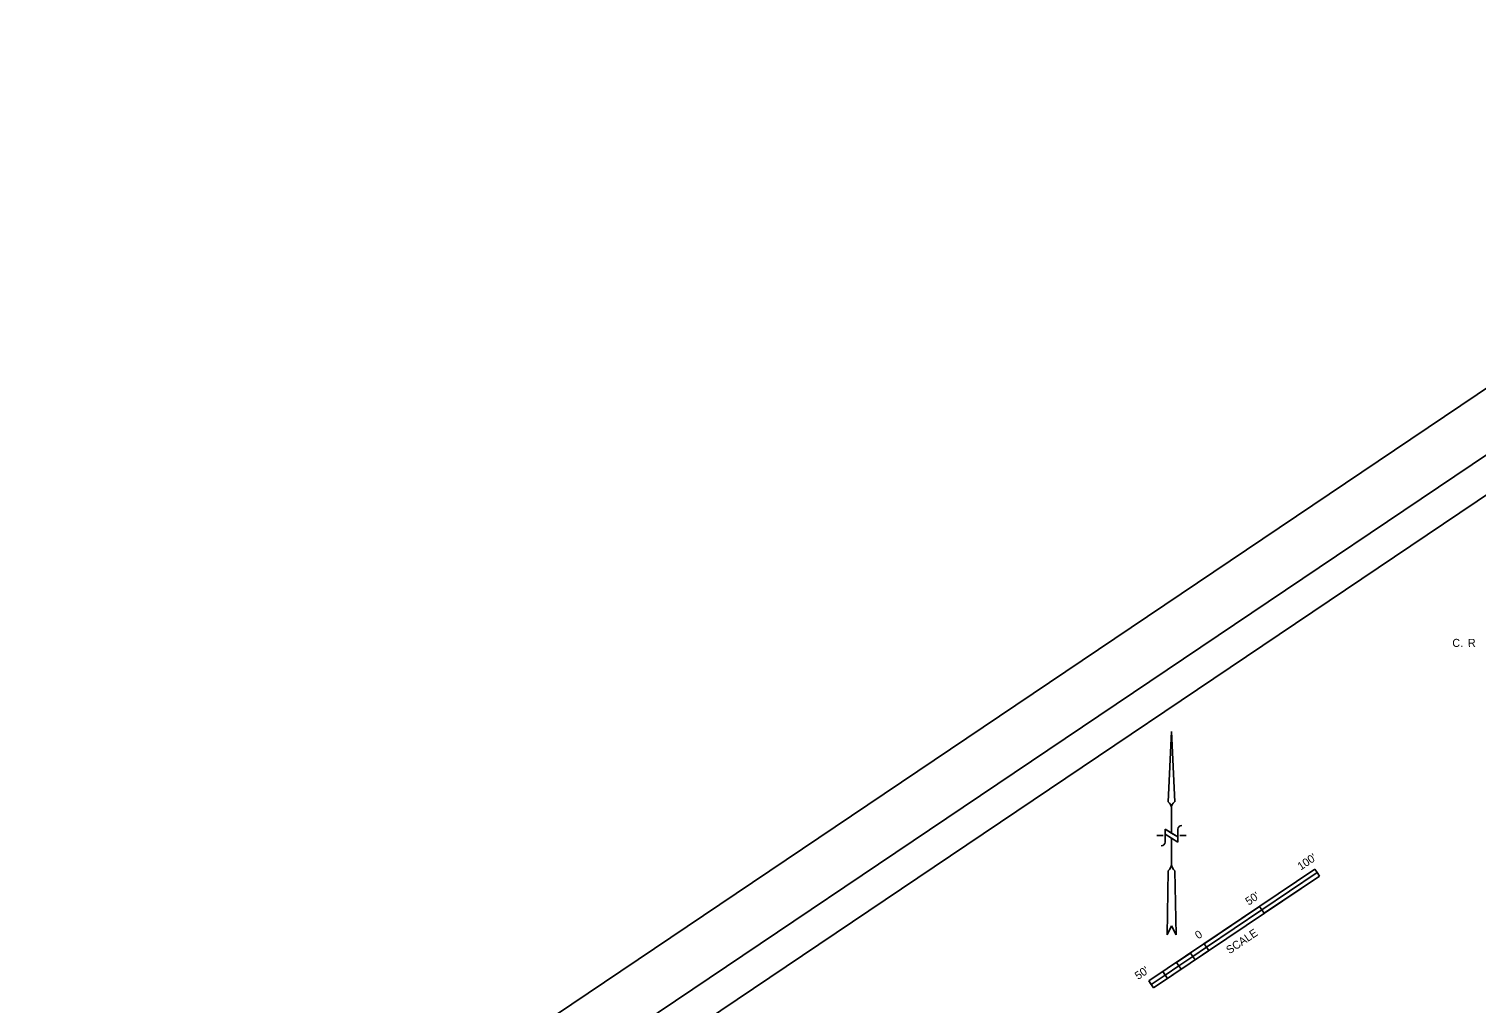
# Model space of a CAD drawing. Extents: x 2150215 to 2152378, y 141356 to 143523.
# Drawn here: x 2150215 to 2151300, y 142627 to 143357 of the extents above; entities that cross this region are included whole.
import ezdxf

# ---------------------------------------------------------------- set-up
doc = ezdxf.new("R2010")
doc.units = 0
for name, color, linetype in [('PR_Align_2_Label', 7, 'Continuous'), ('SHT_North_Arrow', 7, 'Continuous'), ('SHT_Plot_Shape_Full', 7, 'Continuous'), ('SHT_Plot_Shape_Half', 7, 'Continuous'), ('SHT_Scale', 7, 'Continuous'), ('SHT_Sheet_Border', 7, 'Continuous')]:
    doc.layers.add(name, color=color, linetype=linetype)

msp = doc.modelspace()

# ---------------------------------------------------------------- linework, layer by layer
at = {"layer": 'SHT_North_Arrow'}
for p, q in [((2151069.2, 142777.7), (2151071.6, 142830.6)), ((2151071.6, 142830.6), (2151069.2, 142777.7)), ((2151071.6, 142830.6), (2151074, 142777.7)), ((2151074, 142777.7), (2151071.6, 142830.6)), ((2151071.6, 142754.3), (2151071.6, 142773.1)), ((2151065.4, 142752.4), (2151060.6, 142752.4)), ((2151076.4, 142751.5), (2151066.8, 142757.2)), ((2151066.8, 142757.2), (2151076.4, 142751.5)), ((2151066.8, 142757.2), (2151066.8, 142747.6)), ((2151071.6, 142754.3), (2151066.8, 142757.2)), ((2151066.8, 142757.2), (2151066.8, 142753.4)), ((2151076.4, 142747.6), (2151066.8, 142753.4)), ((2151076.4, 142751.5), (2151071.6, 142754.3)), ((2151076.4, 142757.2), (2151076.4, 142747.6)), ((2151082.6, 142752.4), (2151077.8, 142752.4)), ((2151071.6, 142730.8), (2151071.6, 142750.5)), ((2151076.4, 142747.6), (2151076.4, 142751.5)), ((2151068.3, 142678.1), (2151069.2, 142726)), ((2151069.2, 142726), (2151068.3, 142678.1)), ((2151075, 142678.1), (2151074, 142726)), ((2151075, 142678.1), (2151074, 142726)), ((2151068.3, 142678.1), (2151071.6, 142684.8)), ((2151068.3, 142678.1), (2151071.6, 142684.8)), ((2151071.6, 142684.8), (2151075, 142678.1)), ((2151071.6, 142684.8), (2151075, 142678.1))]:
    msp.add_line(p, q, dxfattribs=at)
for points in [[(2151066.8, 142753.4), (2151071.6, 142750.5), (2151076.4, 142747.6)], [(2151071.6, 142730.8), (2151071.6, 142730.8), (2151071.6, 142730.8)]]:
    msp.add_lwpolyline(points, dxfattribs=at)
for centre, radius, start, end in [((2151065.8, 142773.1), 5.76, 0.0232, 54.4034), ((2151065.8, 142773.1), 5.76, 0.0232, 54.4034), ((2151077.3, 142773.1), 5.76, 125.6431, 180.0232), ((2151077.3, 142773.1), 5.76, 125.6431, 180.0232), ((2151079.3, 142757.2), 2.88, 90.0232, 180.0232), ((2151063.9, 142747.6), 2.88, 270.0232, 0.0232), ((2151063.2, 142732), 8.43, 314.9799, 352.4421), ((2151063.2, 142732), 8.43, 314.9799, 352.0822), ((2151080, 142732), 8.43, 187.6043, 225.0665), ((2151080, 142732), 8.43, 187.9642, 225.0665)]:
    msp.add_arc(centre, radius, start, end, dxfattribs=at)
at = {"layer": 'SHT_Plot_Shape_Full'}
msp.add_lwpolyline([(2150214.9, 142351.9), (2151708, 143357.2), (2152378.2, 142361.7), (2150885.1, 141356.5)], close=True, dxfattribs=at)
at = {"layer": 'SHT_Plot_Shape_Half'}
msp.add_lwpolyline([(2150305.9, 142363.4), (2151716.1, 143312.8), (2152330.4, 142400.3), (2150920.2, 141451)], close=True, dxfattribs=at)
at = {"layer": 'SHT_Scale'}
for p, q in [((2151054.7, 142643.5), (2151179.1, 142727.3)), ((2151058.1, 142638.3), (2151182.6, 142722.1)), ((2151097.9, 142668.8), (2151180.8, 142724.7)), ((2151180.8, 142724.7), (2151139.4, 142696.7)), ((2151141.1, 142694.2), (2151182.6, 142722.1)), ((2151179.1, 142727.3), (2151180.8, 142724.7)), ((2151180.8, 142724.7), (2151182.6, 142722.1)), ((2151182.6, 142722.1), (2151180.8, 142724.7)), ((2151137.6, 142699.3), (2151096.1, 142671.4)), ((2151139.4, 142696.7), (2151137.6, 142699.3)), ((2151139.4, 142696.7), (2151137.6, 142699.3)), ((2151097.9, 142668.8), (2151139.4, 142696.7)), ((2151141.1, 142694.2), (2151139.4, 142696.7)), ((2151139.4, 142696.7), (2151141.1, 142694.2)), ((2151087.5, 142661.8), (2151097.9, 142668.8)), ((2151097.9, 142668.8), (2151087.5, 142661.8)), ((2151089.3, 142659.2), (2151099.6, 142666.2)), ((2151097.9, 142668.8), (2151096.1, 142671.4)), ((2151096.1, 142671.4), (2151097.9, 142668.8)), ((2151099.6, 142666.2), (2151097.9, 142668.8)), ((2151099.6, 142666.2), (2151097.9, 142668.8)), ((2151066.8, 142647.9), (2151077.1, 142654.9)), ((2151077.1, 142654.9), (2151066.8, 142647.9)), ((2151085.8, 142664.4), (2151075.4, 142657.4)), ((2151075.4, 142657.4), (2151078.9, 142652.3)), ((2151075.4, 142657.4), (2151078.9, 142652.3)), ((2151075.4, 142657.4), (2151077.1, 142654.9)), ((2151077.1, 142654.9), (2151087.5, 142661.8)), ((2151077.1, 142654.9), (2151087.5, 142661.8)), ((2151078.9, 142652.3), (2151077.1, 142654.9)), ((2151085.8, 142664.4), (2151089.3, 142659.2)), ((2151087.5, 142661.8), (2151085.8, 142664.4)), ((2151087.5, 142661.8), (2151089.3, 142659.2)), ((2151065, 142650.5), (2151054.7, 142643.5)), ((2151054.7, 142643.5), (2151058.1, 142638.3)), ((2151054.7, 142643.5), (2151056.4, 142640.9)), ((2151056.4, 142640.9), (2151066.8, 142647.9)), ((2151056.4, 142640.9), (2151066.8, 142647.9)), ((2151065, 142650.5), (2151068.5, 142645.3)), ((2151066.8, 142647.9), (2151065, 142650.5)), ((2151066.8, 142647.9), (2151068.5, 142645.3)), ((2151068.5, 142645.3), (2151078.9, 142652.3))]:
    msp.add_line(p, q, dxfattribs=at)
at = {"layer": 'SHT_Sheet_Border'}
msp.add_lwpolyline([(2152293.6, 142405.7), (2150987.1, 141526.1), (2150400.7, 142397.1), (2151707.2, 143276.7)], close=True, dxfattribs=at)

# ---------------------------------------------------------------- texts
at = {"layer": 'PR_Align_2_Label'}
for s, p in [('C', (2151282.2, 142893.9)), ('.', (2151288.1, 142893.9)), ('R', (2151293.9, 142893.9))]:
    msp.add_text(s, height=6, rotation=0.4098, dxfattribs=at).set_placement(p)
at = {"layer": 'SHT_Scale'}
for s, p in [("100'", (2151168.6, 142726.2)), ("50'", (2151129.5, 142699.9)), ('0', (2151091.7, 142674.5)), ('SCALE', (2151115.1, 142663.4)), ("50'", (2151046.6, 142644.1))]:
    msp.add_text(s, height=6, rotation=33.9498, dxfattribs=at).set_placement(p)

doc.saveas('drawing.dxf')
